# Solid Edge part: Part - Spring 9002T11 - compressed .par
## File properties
Author: hhakima
Template: Normal.par
Last saved by: Houman
Revision: 7
Application: Solid Edge
Material: Stainless steel
Face Style: Steel
Fill Style: ANSI32(Steel)
Virtual Style: Stainless steel
Coef. of Thermal Exp: 1.6e-05
Thermal Conductivity: 17.0
Specific Heat: 502.0
Modulus of Elasticity: 193053196000.0
Poission's Ratio: 0.29
Yield Stress: 310264065.0
Ultimate Stress: 641212401.0
Elongation: 0.0
Density: 7750.000 kg/m^3
Accuracy: 0.990
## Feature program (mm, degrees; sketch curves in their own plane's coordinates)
body "unnamed Body 1"
sketch for "unnamed Cutout 1" plane through (0.1006, 6.35, 0.7458) normal (0, 1, 0) x-axis (1, 0, 0)
  circle centre (-0.1006, 0.7458) radius 1.9848
extrude "unnamed Cutout 1" cut finite 3.55 along -normal
sketch for "ExtrudedProtrusion_1" plane through (0.1018, 0, -0.7456) normal (0, -1, 0) x-axis (1, 0, 0)
  circle centre (-0.1018, 0.7456) radius 0.05
extrude "ExtrudedProtrusion_1" add finite 1 along -normal
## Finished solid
Body 1: solid body, 10 faces, 13 edges, 6 vertices, 2 separate solids.
  Faces by surface: plane 5, spline 4, cylinder 1
  Edges by curve: spline 6, circle 3, intersection 3, line 1
Bounding box of the edges (mm; curved faces can reach further): 3.048 x 2.800 x 3.048, from (-1.524, 0, -1.524) to (1.524, 2.8, 1.524).
Cylindrical faces by radius (mm): R0.05 x1
Planar faces by outward normal: +y 2, +z 1, -y 2
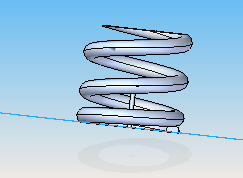
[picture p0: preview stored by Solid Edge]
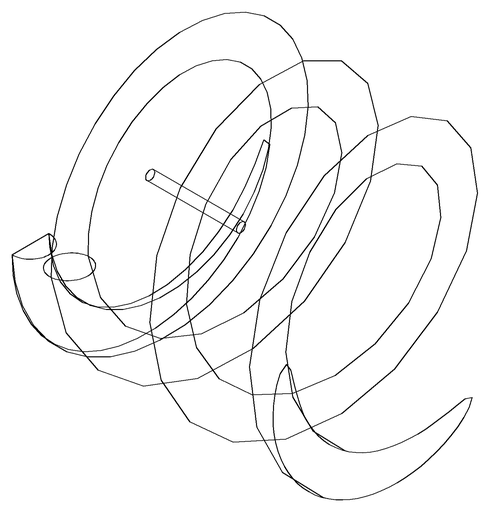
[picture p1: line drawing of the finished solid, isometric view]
